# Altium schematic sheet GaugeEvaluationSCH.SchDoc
size 431 x 279 mm; Date: Not shown in title block; ApprovedBy: Not shown in title block; CheckedBy: Not shown in title block; Author: Not shown in title block; CompanyName: Not shown in title block; Engineer: Not shown in title block; Organization: Not shown in title block; Address1: Not shown in title block; Address2: Not shown in title block; Address3: Not shown in title block; Address4: Not shown in title block; DocumentNumber: 2; Revision: Use project parameter SCH_Rev; SheetNumber: 2; SheetTotal: 3; PageSetup: Record=PageOptions¦CenterHorizontal=True¦CenterVertical=True¦PrintScale=1.00¦XCorrection=1.00¦YCorrection=1.00¦PrintKind=0¦BorderSize=5000000¦LeftOffset=0¦BottomOffset=0¦Orientation=2¦PaperLength=1000¦PaperWidth=1000¦Scale=100¦PaperSource=15¦PrintQuality=600¦MediaType=1¦DitherType=10¦PaperKind=Letter¦PrintScaleMode=1
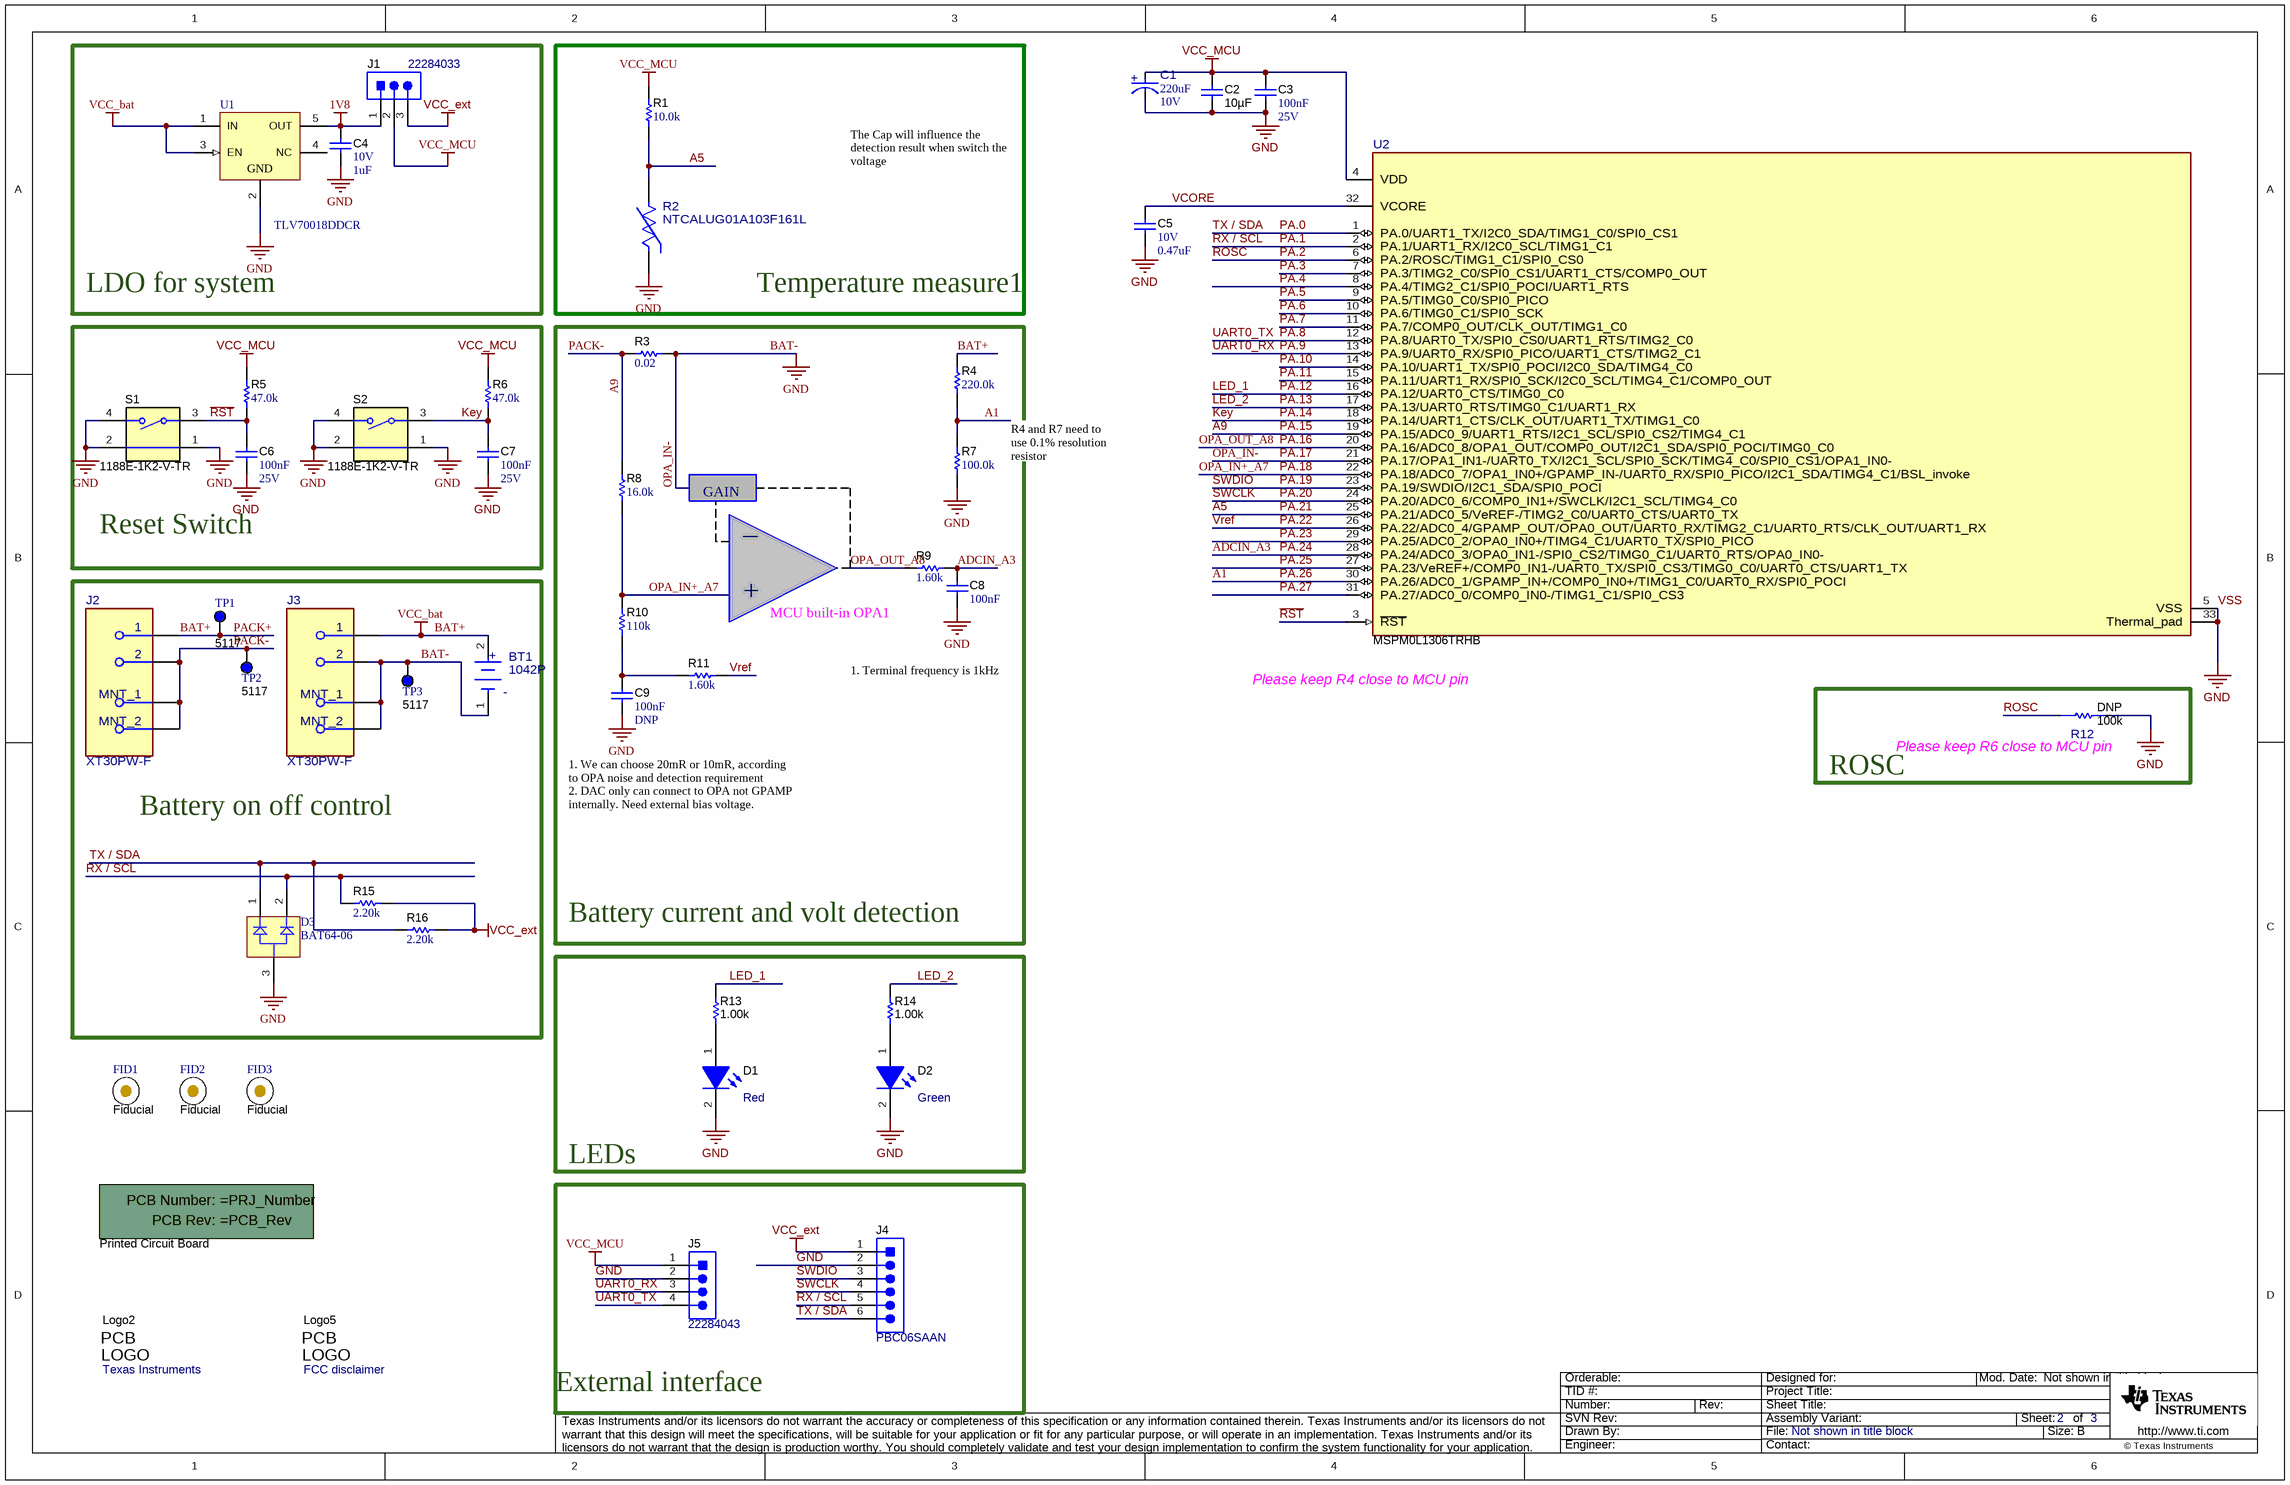
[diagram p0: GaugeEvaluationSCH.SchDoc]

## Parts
!PCB1  Printed Circuit Board  (mechanical)
BT1  1042P  [FP-1042P_BT_HOLDER-MFG]
C1  ValueDisplayed: 220uF  VDC_V: 10V  [FP-TAJB475K010RNJ_1210-MFG]  (hidden comment: TAJB475K010RNJ)
C2  ValueDisplayed: 10µF  [0603]  (hidden comment: GRM188R61A106KAALD)
C3  Cap_F: 100nF  VDC_V: 25V  [0603]  (hidden comment: C0603X104K3RACTU)
C4  VDC_V: 10V  ValueDisplayed: 1uF  [0603]  (hidden comment: C1608X5R1A105K080AC)
C5  VDC_V: 10V  ValueDisplayed: 0.47uF  [0603]  (hidden comment: C0603C474K8PACTU)
C6  Cap_F: 100nF  VDC_V: 25V  [0603]  (hidden comment: C0603X104K3RACTU)
C7  Cap_F: 100nF  VDC_V: 25V  [0603]  (hidden comment: C0603X104K3RACTU)
C8  Cap_F: 100nF  [0603]  (hidden comment: C0603X104K3RACTU)
C9  Cap_F: 100nF  VDC_V: DNP  [0603]  (hidden comment: C0603X104K3RACTU)
D1  value Red  [LED_SMLD12_RED]  (hidden comment: SML-D12U1WT86)
D2  value Green  [LED_SMLD12_RED]  (hidden comment: SML-D12U1WT86)
D3  BAT64-06  [INF-SOT23_M]
FID1  Fiducial  [Fiducial10-30]
FID2  Fiducial  [Fiducial10-30]
FID3  Fiducial  [Fiducial10-30]
J1  22284033  [Molex_0022284033]
J2  XT30PW-F  [FP-XT30PW-F_CONN_SOCKET_DC2-MFG]
J3  XT30PW-F  [FP-XT30PW-F_CONN_SOCKET_DC2-MFG]
J4  PBC06SAAN  [Sullins_PxC06SAAN]
J5  22284043  [Molex_0022284043]
Logo2  Texas Instruments  [TI_Horizontal_Overlay_Small]  (no BOM)
Logo5  FCC disclaimer  [FCC_disclaimer]  (no BOM)
R1  value 10.0k  [0603]  (hidden comment: RNCF0603TKY10K0)
R2  NTCALUG01A103F161L  [FP-NTCALUG01A103F161L_PTH_7MM2_5MM6-MFG]
R3  ValueDisplayed: 0.02  [1210]  (hidden comment: ERJ-L14KF20MU)
R4  ValueDisplayed: 220.0k  [0603]  (hidden comment: RG1608P-223-B-T5)
R5  ValueDisplayed: 47.0k  [0603]  (hidden comment: RT0603BRD0747KL)
R6  ValueDisplayed: 47.0k  [0603]  (hidden comment: RT0603BRD0747KL)
R7  ValueDisplayed: 100.0k  [0603]  (hidden comment: RG1608P-104-B-T5)
R8  ValueDisplayed: 16.0k  [0603]  (hidden comment: ERJ3EKF1602V)
R9  ValueDisplayed: 1.60k  [0603]  (hidden comment: RG1608P-162-B-T5)
R10  ValueDisplayed: 110k  [0603]  (hidden comment: RC0603FR-07115KL)
R11  ValueDisplayed: 1.60k  [0603]  (hidden comment: RG1608P-162-B-T5)
R12  value 100k  VDC_V: DNP  [FP-RN73C1J100KBTG_0603-MFG]  (hidden comment: RN73C1J100KBTG)
R13  ValueDisplayed: 1.00k  [0603]  (hidden comment: RC0603FR-071KL)
R14  ValueDisplayed: 1.00k  [0603]  (hidden comment: RC0603FR-071KL)
R15  ValueDisplayed: 2.20k  [0603]  (hidden comment: RC0603FR-072K2L)
R16  ValueDisplayed: 2.20k  [0603]  (hidden comment: RC0603FR-072K2L)
S1  1188E-1K2-V-TR  [SW_1188E]
S2  1188E-1K2-V-TR  [SW_1188E]
TP1  5117  [Keystone5117]
TP2  5117  [Keystone5117]
TP3  5117  [Keystone5117]
U1  TLV70018DDCR  [DDC0005A_N]
U2  MSPM0L1306TRHB  [RHB0032E-IPC_A]

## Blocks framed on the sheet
LDO for system: C4 J1 U1
Temperature measure1: R1 R2
Reset Switch: C6 C7 R5 R6 S1 S2
Battery on off control: BT1 D3 J2 J3 R15 R16 TP1-TP3
ROSC: R12
LEDs: D1 D2 R13 R14
External interface: J4 J5

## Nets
1V8: C4.1 J1.1 U1.5(OUT)
BAT+: BT1.2(ANODE) J2.1 J3.1 R4.2 TP1.1 U1.1(IN) U1.3(EN)  [also labelled PACK+, VCC_bat]
BAT-: BT1.1(CATHODE) C1.1(CATHODE) C2.1 C3.2 C4.2 C5.2 C6.2 C7.2 C8.2 C9.2 D1.2(K) D2.2(K) D3.3(A) J3.2 J3.3(MNT_1) J3.4(MNT_2) J4.2 J5.2 R2.1 R3.2 R7.1 R12.2 S1.1 S1.2 S1.4 S2.1 S2.2 S2.4 TP3.1 U1.2(GND) U2.5(VSS) U2.21(PA.17/OPA1_IN1-/UART0_TX/I2C1_SCL/SPI0_SCK/TIMG4_C0/SPI0_CS1/OPA1_IN0-) U2.33(Thermal_pad)  [also labelled GND, OPA_IN-, PA.17, VSS]
VCC_ext: J1.3 J4.1 R15.2 R16.2
VCC_MCU: C1.2(ANODE) C2.2 C3.1 J1.2 J5.1 R1.2 R5.2 R6.2 U2.4(VDD)
A1: R4.1 R7.2 U2.30(PA.26/ADC0_1/GPAMP_IN+/COMP0_IN0+/TIMG1_C0/UART0_RX/SPI0_POCI)  [also labelled PA.26]
A5: R1.1 R2.2 U2.25(PA.21/ADC0_5/VeREF-/TIMG2_C0/UART0_CTS/UART0_TX)  [also labelled PA.21]
A9: J2.2 J2.3(MNT_1) J2.4(MNT_2) R3.1 R8.2 TP2.1 U2.19(PA.15/ADC0_9/UART1_RTS/I2C1_SCL/SPI0_CS2/TIMG4_C1)  [also labelled PA.15, PACK-]
ADCIN_A3: C8.1 R9.2 U2.28(PA.24/ADC0_3/OPA0_IN1-/SPI0_CS2/TIMG0_C1/UART0_RTS/OPA0_IN0-)  [also labelled PA.24]
Key: C7.1 R6.1 S2.3 U2.18(PA.14/UART1_CTS/CLK_OUT/UART1_TX/TIMG1_C0)  [also labelled PA.14]
LED_1: R13.1 U2.16(PA.12/UART0_CTS/TIMG0_C0)  [also labelled PA.12]
LED_2: R14.1 U2.17(PA.13/UART0_RTS/TIMG0_C1/UART1_RX)  [also labelled PA.13]
OPA_IN+_A7: R8.1 R10.2 U2.22(PA.18/ADC0_7/OPA1_IN0+/GPAMP_IN-/UART0_RX/SPI0_PICO/I2C1_SDA/TIMG4_C1/BSL_invoke)  [also labelled PA.18]
OPA_OUT_A8: R9.1 U2.20(PA.16/ADC0_8/OPA1_OUT/COMP0_OUT/I2C1_SDA/SPI0_POCI/TIMG0_C0)  [also labelled PA.16]
PA.0: D3.1(K1) J4.6 R16.1 U2.1(PA.0/UART1_TX/I2C0_SDA/TIMG1_C0/SPI0_CS1)  [also labelled TX / SDA]
PA.1: D3.2(K2) J4.5 R15.1 U2.2(PA.1/UART1_RX/I2C0_SCL/TIMG1_C1)  [also labelled RX / SCL]
PA.2: R12.1 U2.6(PA.2/ROSC/TIMG1_C1/SPI0_CS0)  [also labelled ROSC]
PA.3: U2.7(PA.3/TIMG2_C0/SPI0_CS1/UART1_CTS/COMP0_OUT)
PA.4: U2.8(PA.4/TIMG2_C1/SPI0_POCI/UART1_RTS)
PA.5: U2.9(PA.5/TIMG0_C0/SPI0_PICO)
PA.6: U2.10(PA.6/TIMG0_C1/SPI0_SCK)
PA.7: U2.11(PA.7/COMP0_OUT/CLK_OUT/TIMG1_C0)
PA.8: J5.4 U2.12(PA.8/UART0_TX/SPI0_CS0/UART1_RTS/TIMG2_C0)  [also labelled UART0_TX]
PA.9: J5.3 U2.13(PA.9/UART0_RX/SPI0_PICO/UART1_CTS/TIMG2_C1)  [also labelled UART0_RX]
PA.10: U2.14(PA.10/UART1_TX/SPI0_POCI/I2C0_SDA/TIMG4_C0)
PA.11: U2.15(PA.11/UART1_RX/SPI0_SCK/I2C0_SCL/TIMG4_C1/COMP0_OUT)
PA.19: J4.3 U2.23(PA.19/SWDIO/I2C1_SDA/SPI0_POCI)  [also labelled SWDIO]
PA.20: J4.4 U2.24(PA.20/ADC0_6/COMP0_IN1+/SWCLK/I2C1_SCL/TIMG4_C0)  [also labelled SWCLK]
PA.22: R11.2 U2.26(PA.22/ADC0_4/GPAMP_OUT/OPA0_OUT/UART0_RX/TIMG2_C1/UART0_RTS/CLK_OUT/UART1_RX)  [also labelled Vref]
PA.23: U2.29(PA.25/ADC0_2/OPA0_IN0+/TIMG4_C1/UART0_TX/SPI0_PICO)
PA.25: U2.27(PA.23/VeREF+/COMP0_IN1-/UART0_TX/SPI0_CS3/TIMG0_C0/UART0_CTS/UART1_TX)
PA.27: U2.31(PA.27/ADC0_0/COMP0_IN0-/TIMG1_C1/SPI0_CS3)
~{RST}: C6.1 R5.1 S1.3 U2.3(~{RST})
VCORE: C5.1 U2.32(VCORE)
NetC9_1: C9.1 R10.1 R11.1
NetD1_1: D1.1(A) R13.2
NetD2_1: D2.1(A) R14.2

Not connected (* = marked no-connect by the designer): U1 4(NC)

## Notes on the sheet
- The Cap will influence the detection result when switch the voltage
- GAIN
- R4 and R7 need to use 0.1% resolution resistor
- _
- +
- MCU built-in OPA1
- 1. Terminal frequency is 1kHz
- (near U2) Please keep R4 close to MCU pin
- (near R12) Please keep R6 close to MCU pin
- 1. We can choose 20mR or 10mR, according to OPA noise and detection requirement
  2. DAC only can connect to OPA not GPAMP internally. Need external bias voltage.
- Battery current and volt detection

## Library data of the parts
!PCB1 = CMP-0003618-2: Manufacturer: Any
BT1 = CMP-0092114-1: Battery Holder (Open) 18650 1 Cell SMD (SMT) Tab; Manufacturer: Keystone; ContactFinish: Gold,Nickel; AEC Qualified: No; SizeZ_mm: 15.11mm; Conn Orientation: Horizontal
C1 = CMP-0089269-1: 220µF Molded Tantalum Capacitors 10V 1411 (3528 Metric), 1210 4Ohm; Manufacturer: AVX Corporation; SizeZ_mm: 2.1mm; Life: 1000Hours; AEC Qualified: No; Dissipation Factor: 6%; IRMS_A: 146mA; Tolerance_%: 10%; Esr: 4
C2 = CMP-0086193-1: CAP, CERM, 10 µF, 10 V,+/- 10%, X5R, 0603; Manufacturer: MuRata; SizeArea_mm2: 1.28; SizeY_mm: 0.8; TaMax_C: 85°C; TaMin_C: -55°C; Polarized: N; Value2: 10V; SizeAreaWB_mm2: 4.68; SizeZ_mm: 1; SizeX_mm: 1.6; AEC Category: Q200; U/M: EA; Value: 10uF
C3 C6 C7 = CMP-0006979-3: CAP, CERM, 0.1 uF, 25 V, +/- 10%, X7R, 0603; Manufacturer: Kemet; TaMin_C: -55°C; Polarized: N; SizeAreaWB_mm2: 4.68; Value1: Unknown; U/M: EA; Value: 0.1uF; TaMax_C: 125°C; SizeZ_mm: 1; SizeX_mm: 1.6; SizeY_mm: 0.8; SizeArea_mm2: 1.28; AEC Category: Q200
C4 = CMP-0007002-5: CAP, CERM, 1 uF, 10 V, +/- 10%, X5R, 0603; Manufacturer: TDK; TaMin_C: -55°C; Polarized: N; SizeAreaWB_mm2: 4.68; Value1: Unknown; U/M: EA; Value: 1uF; TaMax_C: 85°C; SizeZ_mm: 1; SizeX_mm: 1.6; SizeY_mm: 0.8; SizeArea_mm2: 1.28; Cap_F: 1µF; AEC Category: Q200
C5 = CMP-0006945-1: CAP, CERM, 0.47 uF, 10 V, +/- 10%, X5R, 0603; Manufacturer: Kemet; TaMin_C: -55°C; Polarized: N; SizeAreaWB_mm2: 4.68; Value1: Unknown; U/M: EA; Value: 0.47uF; TaMax_C: 85°C; SizeZ_mm: 1; SizeX_mm: 1.6; SizeY_mm: 0.8; SizeArea_mm2: 1.28; Cap_F: 470nF; AEC Category: Q200
C8 = CMP-0006979-3: CAP, CERM, 0.1 uF, 25 V, +/- 10%, X7R, 0603; Manufacturer: Kemet; TaMin_C: -55°C; Polarized: N; SizeAreaWB_mm2: 4.68; Value1: Unknown; U/M: EA; Value: 0.1uF; TaMax_C: 125°C; SizeZ_mm: 1; SizeX_mm: 1.6; SizeY_mm: 0.8; Value2: 25V; SizeArea_mm2: 1.28; VDC_V: DNP; AEC Category: Q200
C9 = CMP-0006979-3: CAP, CERM, 0.1 uF, 25 V, +/- 10%, X7R, 0603; Manufacturer: Kemet; TaMin_C: -55°C; Polarized: N; SizeAreaWB_mm2: 4.68; Value1: Unknown; U/M: EA; Value: 0.1uF; TaMax_C: 125°C; SizeZ_mm: 1; SizeX_mm: 1.6; SizeY_mm: 0.8; Value2: 25V; SizeArea_mm2: 1.28; AEC Category: Q200
D1 D2 = CMP-0086209-1: LED, Red, SMD; Manufacturer: Rohm; Vr_V: 5V; SizeX_mm: 1.6; Value2: 2.2V; SizeY_mm: 0.8; Io_A: 20mA; Ir_A: 10mA; SizeArea_mm2: 1.28; SizeZ_mm: 0.65; SizeAreaWB_mm2: 4.68; Value1: 0.054W; Power_TotalModule: 54mW
D3 = CMP-1182-00011-1: Silicon Schottky Diode, SOT23, Reel, Green; Manufacturer: Infineon; Green: TRUE; VF (max): 750Â mV; CT (max): 6Â pF; IF (max): 250Â mA; Configuration: Dual; VR (max): 40Â V
FID1-FID3 = CMP-0077181-1: Fiducial mark.  There is nothing to buy or mount.
J1 = CMP-0055332-1: Header, 2.54mm, 3x1, Tin, TH; Manufacturer: Molex; CNHeader: TRUE; Current_A: 4A; Shrouded: N; Gender: Male; Voltage_V: 250V; Row_Count: 1; Pitch_mm: 2.54; CT: FALSE; Cert_UL: Y
J2 J3 = CMP-0035193-1: Socket, DC supply, XT30, female, PIN: 2, on PCBs, THT, yellow, 15A; Manufacturer: Amass; ContactFinish: Gold; Voltage_V: 500V; AEC Qualified: No; Conn Orientation: Right Angle; DUT-Pitch_mm: 5mm; Is Female: yes; Standoff Height: 0.1mm
J4 = CMP-0054603-1: Header, 2.54mm, 6x1, Gold, TH; Manufacturer: Sullins Connector Solutions; CNHeader: TRUE; Current_A: 3A; Green_Lifecycle: Not Set; Shrouded: N; Gender: Male; Green_REACh: Incomplete; Row_Count: 1; Pitch_mm: 2.54; CT: FALSE; Cert_UL: Y
J5 = CMP-0055331-1: Header, 2.54mm, 4x1, Tin, TH; Manufacturer: Molex; CNHeader: TRUE; Current_A: 4A; Shrouded: N; Gender: Male; Voltage_V: 250V; Row_Count: 1; Pitch_mm: 2.54; CT: FALSE; Cert_UL: Y
Logo2 = CMP-0074838-1: Texas Instrument Corporate Signature; SymbolCreator: a0412235; Lib Reference: TI_Logo
Logo5 = CMP-0074847-1: FCC_disclaimer
R1 = CMP-0023626-3: RES, 10.0 k, 1%, 0.063 W, 0603; Manufacturer: Stackpole Electronics Inc; Power_W: 63mW; TempCo: 5 ppm/C; Value_Code: 10k0; Value1: 0.01%; U/M: EA; Res_ohm: 10k; SizeX_mm: 1.6; SizeY_mm: 0.8; SizeZ_mm: 1; Value2: 0.063W; SizeArea_mm2: 1.28; VDC_V: 50V; AEC Category: Q200
R2 = CMP-0091769-1: NTC Thermistors; NTC Lug 10k 1% 3435K awg#24 PTFE 600V 16; Manufacturer: Vishay; AEC Grade: Grade 1; AEC Qualified: Yes; Res_ohm: 10000Ω
R3 = CMP-0015069-2: RES, 0.02, 1%, 0.33 W, 1210; Manufacturer: Panasonic; Power_W: 330mW; TempCo: 300 ppm/C; SizeAreaWB_mm2: 14.7; Value_Code: R020; U/M: EA; Value: 0.02; EIA_Code: E96; SizeX_mm: 3.2; SizeY_mm: 2.5; SizeZ_mm: 1.35; Value2: 0.33W; SizeArea_mm2: 8; AEC Category: Q200
R4 = CMP-0023474-2: RES, 220.0 k, 0.1%, 0.1 W, 0603; Manufacturer: Susumu Co Ltd; PartNumber: RG1608P-224-B-T5; Power_W: 100mW; TempCo: 25 ppm/C; Value_Code: 220k0; U/M: EA; Value: 220.0k; Res_ohm: 220k; SizeX_mm: 1.6; SizeY_mm: 0.8; SizeZ_mm: 1; Value2: 0.1W; SizeArea_mm2: 1.28; VDC_V: 75V; AEC Category: Q200
R5 = CMP-0024267-2: RES, 47.0 k, 1%, 0.1 W, 0603; Manufacturer: Yageo America; Power_W: 100mW; TempCo: 25 ppm/C; Value_Code: 47k0; Value1: 0.1%; U/M: EA; Value: 47.0k; EIA_Code: E192; Res_ohm: 47k; SizeX_mm: 1.6; SizeY_mm: 0.8; SizeZ_mm: 1; Value2: 0.1W; SizeArea_mm2: 1.28; VDC_V: 75V; AEC Category: Q200
R6 = CMP-0024267-2: RES, 47.0 k, 1%, 0.1 W, 0603; Manufacturer: Yageo America; Power_W: 100mW; TempCo: 25 ppm/C; Value_Code: 47k0; U/M: EA; Value: 47.0k; EIA_Code: E192; Tolerance_%: 0.1%; Res_ohm: 47k; SizeX_mm: 1.6; SizeY_mm: 0.8; SizeZ_mm: 1; Value2: 0.1W; SizeArea_mm2: 1.28; VDC_V: 75V; AEC Category: Q200
R7 = CMP-0023404-1: RES, 100.0 k, 0.1%, 0.1 W, 0603; Manufacturer: Susumu Co Ltd; Power_W: 100mW; TempCo: 25 ppm/C; Value_Code: 100k0; U/M: EA; Value: 100.0k; EIA_Code: E192; Res_ohm: 10k; SizeX_mm: 1.6; SizeY_mm: 0.8; SizeZ_mm: 1; Value2: 0.1W; SizeArea_mm2: 1.28; VDC_V: 75V; AEC Category: Q200
R8 = CMP-0078661-1: RES, 16.0 k, 1%, 0.1 W, AEC-Q200 Grade 0, 0603; Manufacturer: Panasonic; Power_W: 100mW; TempCo: 100 ppm/C; Value_Code: 16k0; Value: 16.0k; Res_ohm: 16k; SizeX_mm: 1.6; SizeY_mm: 0.8; SizeZ_mm: 1; Value2: 0.1W; SizeArea_mm2: 1.28; AEC Qualified: Y; AEC Grade: 0; AEC Category: Q200
R9 = CMP-0023448-3: RES, 1.60 k, 0.1%, 0.1 W, 0603; Manufacturer: Susumu Co Ltd; Power_W: 100mW; TempCo: 25 ppm/C; Value_Code: 1k60; U/M: EA; Value: 1.60k; EIA_Code: E192; Res_ohm: 1.6k; SizeX_mm: 1.6; SizeY_mm: 0.8; SizeZ_mm: 1; Value2: 0.1W; SizeArea_mm2: 1.28; VDC_V: DNP; AEC Category: Q200
R10 = CMP-0022756-4: RES, 110 k, 1%, 0.1 W, 0603; Manufacturer: Yageo; Power_W: 100mW; TempCo: 100 ppm/C; Value: 110k; EIA_Code: E96; SizeX_mm: 1.6; SizeY_mm: 0.8; SizeZ_mm: 1; Value2: 0.1W; SizeArea_mm2: 1.28; AEC Qualified: N; VDC_V: 75V; AEC Category: Q200; SizeAreaWB_mm2: 4.68
R11 = CMP-0023448-3: RES, 1.60 k, 0.1%, 0.1 W, 0603; Manufacturer: Susumu Co Ltd; Power_W: 100mW; TempCo: 25 ppm/C; Value_Code: 1k60; U/M: EA; Value: 1.60k; EIA_Code: E192; Res_ohm: 1.6k; SizeX_mm: 1.6; SizeY_mm: 0.8; SizeZ_mm: 1; Value2: 0.1W; SizeArea_mm2: 1.28; VDC_V: 75V; AEC Category: Q200
R12 = CMP-0093027-1: Thin Film Resistors RN 0603 100KΩ 0.1% 10ppm/°C; Manufacturer: TE Connectivity; AEC Qualified: No; SizeZ_mm: 0.55mm; Power_W: 63mW
R13 R14 = CMP-0022895-5: RES, 1.00 k, 1%, 0.1 W, 0603; Manufacturer: Yageo; Power_W: 100mW; TempCo: 100 ppm/C; Value_Code: 1k00; Value: 1.00k; EIA_Code: E96; Res_ohm: 1k; SizeX_mm: 1.6; SizeY_mm: 0.8; SizeZ_mm: 1; Value2: 0.1W; SizeArea_mm2: 1.28; AEC Qualified: N; VDC_V: 75V; AEC Category: Q200; SizeAreaWB_mm2: 4.68
R15 R16 = CMP-0022986-5: RES, 2.20 k, 1%, 0.1 W, 0603; Manufacturer: Yageo; Power_W: 100mW; TempCo: 100 ppm/C; Value_Code: 2k20; Value: 2.20k; Res_ohm: 2.2k; SizeX_mm: 1.6; SizeY_mm: 0.8; SizeZ_mm: 1; Value2: 0.1W; SizeArea_mm2: 1.28; AEC Qualified: N; VDC_V: 75V; AEC Category: Q200; SizeAreaWB_mm2: 4.68
S1 S2 = CMP-0002328-1: Switch, SPST, 0.05 A, 12 VDC, SMD; Manufacturer: Diptronics; CurrentRating_mA: 50A; PositionCount: 1; SizeX_mm: 7.8; SizeY_mm: 3.5; SizeArea_mm2: 27.3; VDC_V: 12V; SizeAreaWB_mm2: 53.9
TP1-TP3 = CMP-0055154-1: Test Point, Miniature, Blue, TH; Manufacturer: Keystone; CNHeader: FALSE; Green_Lifecycle: Active; Green_REACh: Passed; ContactFinish: Silver; CT: TRUE
U1 = CMP-0035825-1: Single Output LDO, 200 mA, Fixed 1.8 V Output, 2 to 5.5 V Input, with Low IQ, 5-pin SOT (DDC), -40 to 125 degC, Green (RoHS & no Sb/Br); Manufacturer: Texas Instruments; Vout Adj(Min)(V): 1.8; Accuracy(%): 2; SubFamily: Single Channel LDO; Vin(Max)(V): 5.5; Iout(Max)(A): 0.2; Iq(Typ)(mA): 0.03; Fixed Output Options(V): 3.3; Vdo(Typ)(mV): 175
U2 = CMP-0092679-1: Mixed-Signal Microcontroller VQFN32; Manufacturer: Texas Instruments; Core Architecture: ARM Cortex-M0+; Number Of Uart Channels: 2; Interface: I2C,SPI,UART,LIN,IrDA,SMBus,Other; Memory Type: FLASH; Standoff Height: 0mm; TaMin_C: -40°C; Number Of A/D Converters: 1; TaMax_C: +105°C; Min Supply Voltage: 1.62V; Max Supply Voltage: 3.6V; Ram Size: 4KBytes; Memory Size: 64KBytes; Number Of Pwm Channels: 8; Number Of Timers/Counters: 4; SizeZ_mm: 1mm; Number Of Adc Channels: 10; AEC Qualified: No; Number Of I/Os: 28; Frequency_Fixed: 32MHz; Data Bus Width: 32bits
